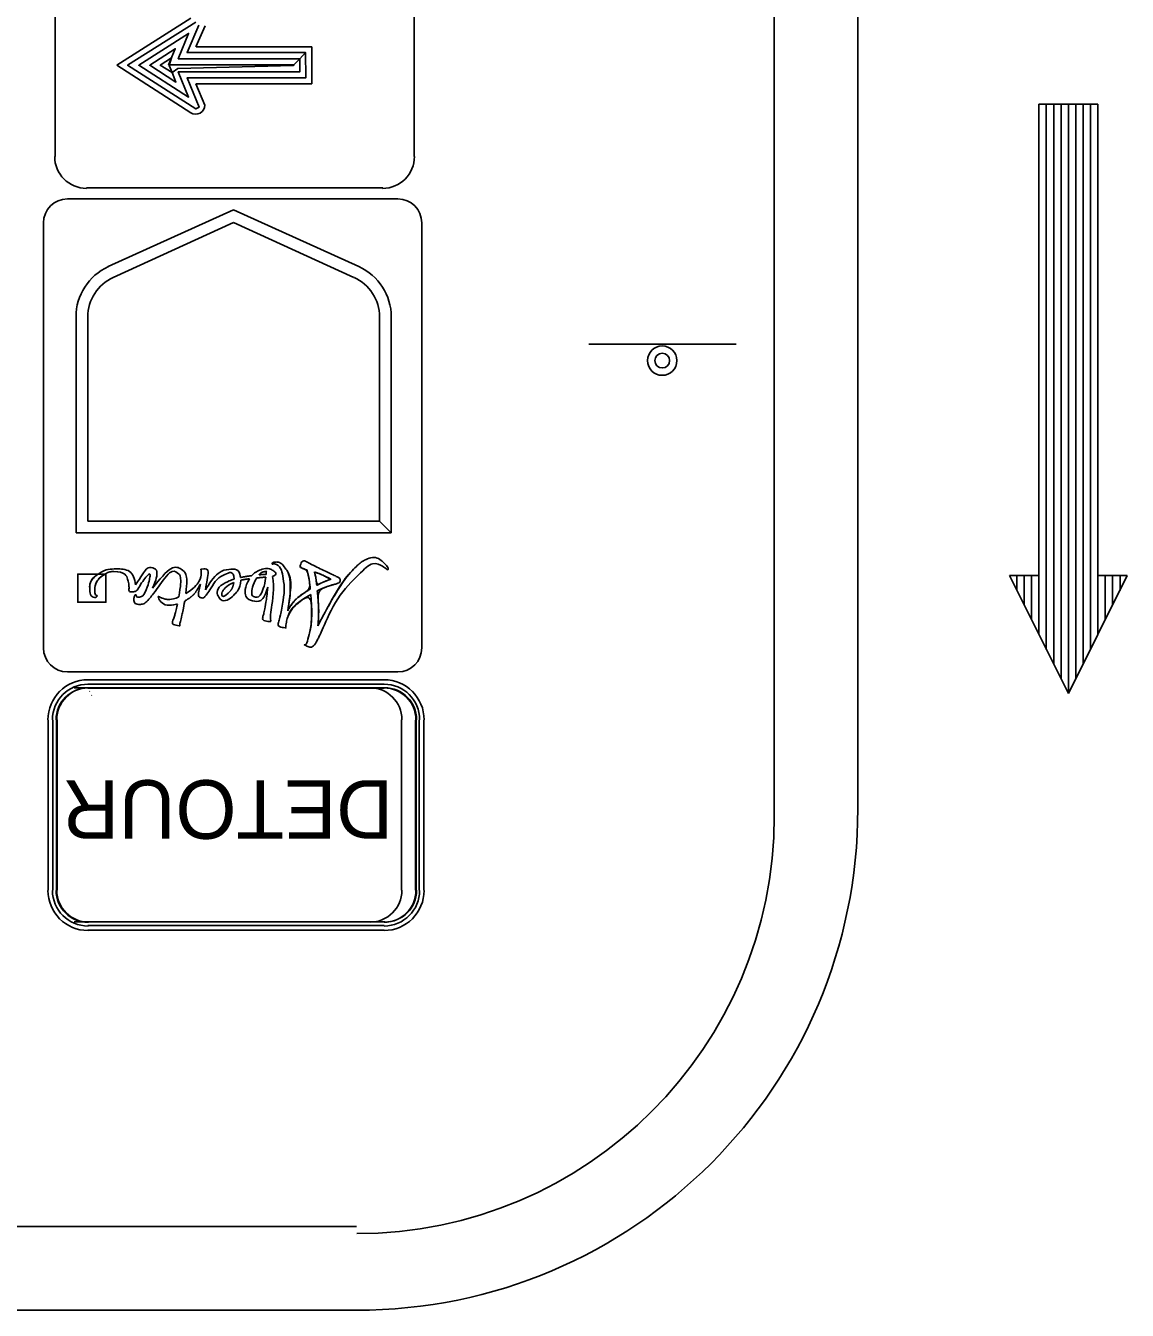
# Model space of a CAD drawing. Extents: x 1806 to 2022, y 110 to 389.
# Drawn here: x 1952.54 to 1968.49, y 225.81 to 244.41 of the extents above; entities that cross this region are included whole.
import ezdxf

# ---------------------------------------------------------------- set-up
doc = ezdxf.new("R2010")
doc.units = 0
for name, color, linetype in [('Level 10', 7, 'Continuous'), ('Level 2', 7, 'Continuous'), ('Level 44', 7, 'Continuous'), ('Level 50', 7, 'Continuous'), ('Level 53', 7, 'Continuous')]:
    doc.layers.add(name, color=color, linetype=linetype)

msp = doc.modelspace()

# ---------------------------------------------------------------- linework, layer by layer
at = {"layer": 'Level 10'}
for p, q in [((1963.38, 232.973), (1963.38, 272.1)), ((1964.59, 233.074), (1964.59, 272.1)), ((1957.331, 227.026), (1895.86, 227.026)), ((1957.331, 225.815), (1895.86, 225.815))]:
    msp.add_line(p, q, dxfattribs=at)
for centre, radius in [((1957.332, 233.074), 7.258), ((1957.332, 232.973), 6.048)]:
    msp.add_arc(centre, radius, 270, 360, dxfattribs=at)
at = {"layer": 'Level 2'}
for p, q in [((1957.928, 241.904), (1953.143, 241.904)), ((1953.735, 240.923), (1955.55, 241.748)), ((1955.55, 241.748), (1957.364, 240.923)), ((1952.796, 235.403), (1952.796, 241.557)), ((1955.55, 241.56), (1953.806, 240.767)), ((1957.293, 240.767), (1955.55, 241.56)), ((1958.275, 235.403), (1958.275, 241.557)), ((1953.267, 237.068), (1953.267, 240.196)), ((1953.438, 240.196), (1953.438, 237.24)), ((1957.661, 237.24), (1957.661, 240.196)), ((1957.833, 240.196), (1957.833, 237.068)), ((1953.438, 237.24), (1957.661, 237.24)), ((1957.833, 237.068), (1957.661, 237.24)), ((1957.661, 237.24), (1957.833, 237.068)), ((1957.833, 237.068), (1953.267, 237.068)), ((1957.928, 235.056), (1953.143, 235.056)), ((1957.928, 235.056), (1953.143, 235.056))]:
    msp.add_line(p, q, dxfattribs=at)
for centre, radius, start, end in [((1953.143, 241.557), 0.347, 90, 180), ((1957.928, 241.557), 0.347, 360, 90), ((1954.066, 240.196), 0.799, 114.4568, 180), ((1957.034, 240.196), 0.799, 360, 65.5432), ((1954.066, 240.196), 0.628, 114.4568, 180), ((1957.034, 240.196), 0.628, 360, 65.5432), ((1953.143, 235.403), 0.347, 180, 270), ((1957.928, 235.403), 0.347, 270, 360)]:
    msp.add_arc(centre, radius, start, end, dxfattribs=at)
at = {"layer": 'Level 44'}
for p, q in [((1952.964, 244.984), (1952.964, 242.519)), ((1958.163, 242.519), (1958.163, 244.984)), ((1954.931, 244.522), (1953.856, 243.839)), ((1955.004, 244.103), (1955.136, 244.411)), ((1956.681, 244.103), (1955.008, 244.103)), ((1956.681, 243.57), (1956.681, 244.103)), ((1953.856, 243.839), (1954.931, 243.152)), ((1955.132, 243.263), (1955.004, 243.57)), ((1955.004, 243.57), (1956.681, 243.57)), ((1953.42, 242.062), (1957.711, 242.062)), ((1962.828, 239.802), (1960.695, 239.802)), ((1953.437, 234.942), (1957.728, 234.942)), ((1953.437, 234.877), (1957.728, 234.877)), ((1957.529, 234.825), (1953.238, 234.825)), ((1953.441, 234.825), (1953.437, 234.823)), ((1953.437, 234.823), (1957.728, 234.823)), ((1953.437, 234.823), (1957.728, 234.823)), ((1953.447, 234.825), (1957.738, 234.825)), ((1953.465, 234.777), (1953.461, 234.775)), ((1953.494, 234.719), (1953.49, 234.717)), ((1955.362, 234.829), (1955.362, 234.829)), ((1955.362, 234.829), (1955.362, 234.829)), ((1955.372, 234.831), (1955.372, 234.831)), ((1955.604, 234.831), (1955.604, 234.831)), ((1952.866, 231.895), (1952.866, 234.36)), ((1952.931, 231.895), (1952.931, 234.36)), ((1952.985, 231.895), (1952.985, 234.36)), ((1952.985, 231.895), (1952.985, 234.36)), ((1952.995, 231.897), (1952.995, 234.362)), ((1957.981, 231.897), (1957.981, 234.362)), ((1958.184, 234.36), (1958.184, 231.895)), ((1958.184, 234.36), (1958.184, 231.895)), ((1958.194, 234.362), (1958.194, 231.897)), ((1958.238, 234.36), (1958.238, 231.895)), ((1958.303, 234.36), (1958.303, 231.895)), ((1953.238, 231.441), (1957.529, 231.441)), ((1957.728, 231.439), (1953.437, 231.439)), ((1957.728, 231.439), (1953.437, 231.439)), ((1957.728, 231.385), (1953.437, 231.385)), ((1957.738, 231.441), (1953.447, 231.441)), ((1957.728, 231.32), (1953.437, 231.32))]:
    msp.add_line(p, q, dxfattribs=at)
for points in [[(1955, 244.462), (1954.014, 243.839), (1955.004, 243.207), (1955.051, 243.233), (1954.876, 243.655), (1956.595, 243.655), (1956.591, 244.022), (1956.51, 243.933), (1954.748, 243.933), (1954.897, 244.3), (1954.176, 243.839), (1954.897, 243.378), (1954.748, 243.745), (1956.51, 243.745), (1956.51, 243.933), (1956.42, 243.847), (1954.607, 243.847), (1954.705, 244.078), (1954.334, 243.839), (1954.714, 243.596), (1954.658, 243.732), (1954.488, 243.839), (1954.65, 243.946), (1954.616, 243.835), (1954.658, 243.732), (1954.744, 243.792), (1956.416, 243.835), (1956.42, 243.847)], [(1956.591, 244.022), (1954.876, 244.022), (1955.046, 244.419)], [(1956.591, 244.022), (1954.876, 244.022)]]:
    msp.add_lwpolyline(points, dxfattribs=at)
for radius in [0.213, 0.107]:
    msp.add_circle((1961.757, 239.563), radius, dxfattribs=at)
for centre, radius, start, end in [((1955, 243.263), 0.132, 237.5014, 359.8949), ((1953.42, 242.518), 0.462, 180, 270), ((1957.707, 242.518), 0.462, 270, 0), ((1953.441, 234.363), 0.581, 90, 180), ((1953.441, 234.363), 0.516, 90, 180), ((1957.728, 234.363), 0.581, 0, 90), ((1957.728, 234.363), 0.516, 0, 90), ((1953.441, 234.363), 0.462, 90, 180), ((1953.441, 234.363), 0.462, 90, 180), ((1953.451, 234.365), 0.462, 90, 180), ((1957.525, 234.365), 0.462, 0, 90), ((1957.728, 234.363), 0.462, 0, 90), ((1957.728, 234.363), 0.462, 0, 90), ((1957.738, 234.365), 0.462, 0, 90), ((1953.451, 231.896), 0.462, 180, 270), ((1957.525, 231.896), 0.462, 270, 0), ((1957.738, 231.896), 0.462, 270, 360), ((1953.441, 231.894), 0.581, 180, 270), ((1953.441, 231.894), 0.516, 180, 270), ((1953.441, 231.894), 0.462, 180, 270), ((1953.441, 231.894), 0.462, 180, 270), ((1957.728, 231.894), 0.462, 270, 360), ((1957.728, 231.894), 0.581, 270, 360), ((1957.728, 231.894), 0.516, 270, 360), ((1957.728, 231.894), 0.462, 270, 360)]:
    msp.add_arc(centre, radius, start, end, dxfattribs=at)
at = {"layer": 'Level 50'}
for p, q in [((1967.213, 236.45), (1967.213, 243.276)), ((1968.067, 243.276), (1967.213, 243.276)), ((1967.213, 235.596), (1967.213, 243.276)), ((1967.32, 235.383), (1967.32, 243.276)), ((1967.427, 235.17), (1967.427, 243.276)), ((1967.533, 234.956), (1967.533, 243.276)), ((1967.64, 234.743), (1967.64, 243.276)), ((1967.747, 234.956), (1967.747, 243.276)), ((1967.853, 235.17), (1967.853, 243.276)), ((1967.96, 235.383), (1967.96, 243.276)), ((1968.067, 236.45), (1968.067, 243.276)), ((1968.067, 235.596), (1968.067, 243.276)), ((1967.64, 234.743), (1966.787, 236.45)), ((1967.213, 236.45), (1966.787, 236.45)), ((1966.893, 236.236), (1966.893, 236.45)), ((1967, 236.023), (1967, 236.45)), ((1967.107, 235.81), (1967.107, 236.45)), ((1967.64, 234.743), (1968.493, 236.45)), ((1968.493, 236.45), (1968.067, 236.45)), ((1968.173, 235.81), (1968.173, 236.45)), ((1968.28, 236.023), (1968.28, 236.45)), ((1968.387, 236.236), (1968.387, 236.45))]:
    msp.add_line(p, q, dxfattribs=at)
at = {"layer": 'Level 53'}
msp.add_line((1953.587, 236.473), (1953.687, 236.473), dxfattribs=at)
msp.add_lwpolyline([(1953.587, 236.473), (1953.292, 236.473), (1953.292, 236.066), (1953.699, 236.066), (1953.699, 236.473), (1953.687, 236.473)], dxfattribs=at)
for points, degree in [([(1954.13, 236.318), (1954.12, 236.402), (1954.064, 236.547), (1953.838, 236.547), (1953.737, 236.547), (1953.651, 236.518), (1953.587, 236.473)], 3), ([(1954.377, 236.269), (1954.429, 236.387), (1954.459, 236.538), (1954.38, 236.561), (1954.288, 236.588), (1954.215, 236.435), (1954.13, 236.318)], 3), ([(1954.858, 236.193), (1954.876, 236.351), (1954.87, 236.492), (1954.798, 236.537), (1954.666, 236.619), (1954.48, 236.402), (1954.377, 236.269)], 3), ([(1955.143, 236.245), (1955.153, 236.343), (1955.216, 236.557), (1955.108, 236.546), (1955.065, 236.542), (1955.084, 236.535), (1955.081, 236.498), (1955.072, 236.369), (1954.964, 236.26), (1954.858, 236.193)], 3), ([(1955.651, 236.424), (1955.642, 236.496), (1955.596, 236.551), (1955.487, 236.54), (1955.332, 236.526), (1955.195, 236.336), (1955.143, 236.245)], 3), ([(1956.112, 236.44), (1956.158, 236.455), (1956.177, 236.489), (1956.118, 236.526), (1956.077, 236.551), (1955.988, 236.559), (1955.897, 236.515), (1955.865, 236.499), (1955.837, 236.476), (1955.813, 236.45)], 3), ([(1956.141, 236.621), (1956.185, 236.614), (1956.242, 236.555), (1956.259, 236.457), (1956.291, 236.28), (1956.272, 236.106), (1956.22, 235.846), (1956.211, 235.797), (1956.177, 235.712), (1956.284, 235.696), (1956.317, 235.691), (1956.3, 235.707), (1956.309, 235.752), (1956.35, 235.945), (1956.508, 236.085), (1956.667, 236.178), (1956.684, 235.957), (1956.677, 235.711), (1956.635, 235.56), (1956.6, 235.433), (1956.558, 235.457), (1956.61, 235.43), (1956.665, 235.402), (1956.723, 235.439), (1956.771, 235.534), (1956.818, 235.628), (1957.037, 236.143), (1957.386, 236.49), (1957.565, 236.667), (1957.726, 236.576), (1957.759, 236.549), (1957.785, 236.526), (1957.795, 236.561), (1957.762, 236.596), (1957.617, 236.752), (1957.406, 236.662), (1957.33, 236.585), (1957.117, 236.373), (1956.87, 235.916), (1956.77, 235.722), (1956.78, 235.831), (1956.783, 236.014), (1956.762, 236.229), (1956.87, 236.282), (1956.967, 236.313), (1957.013, 236.325), (1957.063, 236.338), (1957.093, 236.358), (1957.094, 236.381), (1957.095, 236.406), (1957.062, 236.427), (1957.014, 236.45), (1956.928, 236.49), (1956.678, 236.609), (1956.616, 236.645), (1956.563, 236.675), (1956.537, 236.651), (1956.522, 236.618), (1956.501, 236.575), (1956.557, 236.55), (1956.612, 236.534), (1956.632, 236.461), (1956.649, 236.364), (1956.66, 236.256), (1956.533, 236.177), (1956.408, 236.073), (1956.335, 235.943), (1956.353, 236.052), (1956.4, 236.422), (1956.283, 236.579), (1956.257, 236.614), (1956.2, 236.652), (1956.145, 236.646), (1956.119, 236.643), (1956.105, 236.626), (1956.108, 236.621), (1956.111, 236.615), (1956.126, 236.623), (1956.141, 236.621)], 3), ([(1956.335, 235.943), (1956.353, 236.052), (1956.4, 236.422), (1956.283, 236.579), (1956.257, 236.614), (1956.2, 236.652), (1956.145, 236.646), (1956.119, 236.643), (1956.105, 236.626), (1956.108, 236.621), (1956.111, 236.615), (1956.126, 236.623), (1956.141, 236.621)], 3), ([(1956.141, 236.621), (1956.185, 236.614), (1956.242, 236.555), (1956.259, 236.457), (1956.291, 236.28), (1956.272, 236.106), (1956.22, 235.846), (1956.211, 235.797), (1956.177, 235.712), (1956.284, 235.696), (1956.317, 235.691), (1956.3, 235.707), (1956.309, 235.752), (1956.35, 235.945), (1956.508, 236.085), (1956.667, 236.178)], 3), ([(1956.762, 236.229), (1956.87, 236.282), (1956.967, 236.313), (1957.013, 236.325), (1957.063, 236.338), (1957.093, 236.358), (1957.094, 236.381), (1957.095, 236.406), (1957.062, 236.427), (1957.014, 236.45), (1956.928, 236.49), (1956.678, 236.609), (1956.616, 236.645), (1956.563, 236.675), (1956.537, 236.651), (1956.522, 236.618), (1956.501, 236.575), (1956.557, 236.55), (1956.612, 236.534)], 3), ([(1956.667, 236.178), (1956.684, 235.957), (1956.677, 235.711), (1956.635, 235.56), (1956.6, 235.433), (1956.558, 235.457), (1956.61, 235.43), (1956.665, 235.402), (1956.723, 235.439), (1956.771, 235.534), (1956.818, 235.628), (1957.037, 236.143), (1957.386, 236.49), (1957.565, 236.667), (1957.726, 236.576), (1957.759, 236.549), (1957.785, 236.526), (1957.795, 236.561), (1957.762, 236.596), (1957.617, 236.752), (1957.406, 236.662), (1957.33, 236.585), (1957.117, 236.373), (1956.87, 235.916), (1956.77, 235.722)], 3), ([(1953.699, 236.066), (1953.699, 236.066), (1953.699, 236.473), (1953.699, 236.473), (1953.699, 236.473), (1953.687, 236.473), (1953.687, 236.473), (1953.599, 236.42), (1953.539, 236.319), (1953.54, 236.235), (1953.54, 236.164), (1953.578, 236.167), (1953.573, 236.157), (1953.561, 236.128), (1953.471, 236.145), (1953.466, 236.246), (1953.461, 236.332), (1953.506, 236.416), (1953.587, 236.473), (1953.587, 236.473), (1953.292, 236.473), (1953.292, 236.473), (1953.292, 236.473), (1953.292, 236.066), (1953.292, 236.066), (1953.292, 236.066), (1953.699, 236.066), (1953.699, 236.066)], 3), ([(1953.687, 236.473), (1953.599, 236.42), (1953.539, 236.319), (1953.54, 236.235), (1953.54, 236.164), (1953.578, 236.167), (1953.573, 236.157), (1953.561, 236.128), (1953.471, 236.145), (1953.466, 236.246), (1953.461, 236.332), (1953.506, 236.416), (1953.587, 236.473)], 3), ([(1953.687, 236.473), (1953.725, 236.495), (1953.768, 236.509), (1953.813, 236.509)], 2), ([(1953.813, 236.509), (1953.98, 236.509), (1954.024, 236.379), (1954.032, 236.315), (1954.037, 236.272), (1954.028, 236.21), (1954.102, 236.218), (1954.153, 236.224), (1954.2, 236.325), (1954.266, 236.41), (1954.322, 236.482), (1954.347, 236.475), (1954.334, 236.413), (1954.318, 236.335), (1954.252, 236.151), (1954.178, 236.138), (1954.143, 236.132), (1954.131, 236.192), (1954.115, 236.154), (1954.099, 236.116), (1954.114, 236.034), (1954.191, 236.034), (1954.245, 236.034), (1954.31, 236.091), (1954.363, 236.157), (1954.41, 236.214), (1954.644, 236.559), (1954.743, 236.485), (1954.789, 236.45), (1954.785, 236.308), (1954.756, 236.141)], 3), ([(1955.068, 236.325), (1955.058, 236.275), (1955.042, 236.219), (1955.041, 236.181), (1955.04, 236.142), (1955.067, 236.133), (1955.077, 236.13), (1955.1, 236.123), (1955.128, 236.135), (1955.156, 236.173), (1955.22, 236.264), (1955.302, 236.408), (1955.426, 236.468), (1955.515, 236.512), (1955.554, 236.468), (1955.556, 236.401)], 3), ([(1955.556, 236.401), (1955.539, 236.396), (1955.523, 236.39), (1955.51, 236.384), (1955.349, 236.313), (1955.293, 236.205), (1955.334, 236.139), (1955.373, 236.077), (1955.484, 236.096), (1955.572, 236.188), (1955.615, 236.234), (1955.649, 236.312), (1955.653, 236.384)], 3), ([(1955.813, 236.45), (1955.76, 236.443), (1955.703, 236.434), (1955.651, 236.424)], 2), ([(1955.653, 236.384), (1955.69, 236.392), (1955.733, 236.399), (1955.78, 236.405)], 2), ([(1955.78, 236.405), (1955.705, 236.282), (1955.711, 236.116), (1955.822, 236.088), (1955.95, 236.056), (1956.015, 236.18), (1956.043, 236.284)], 3), ([(1956.015, 236.429), (1955.998, 236.298), (1955.93, 236.116), (1955.845, 236.146), (1955.797, 236.162), (1955.822, 236.315), (1955.885, 236.417)], 3), ([(1955.885, 236.417), (1955.926, 236.421), (1955.97, 236.425), (1956.015, 236.429)], 2), ([(1955.918, 236.461), (1955.94, 236.486), (1955.965, 236.503), (1955.992, 236.507)], 2), ([(1956.019, 236.469), (1955.996, 236.468), (1955.96, 236.466), (1955.918, 236.461)], 2), ([(1956.043, 236.284), (1956.035, 236.18), (1956.018, 236.054), (1955.994, 235.937), (1955.985, 235.888), (1955.951, 235.802), (1956.058, 235.786), (1956.092, 235.781), (1956.086, 235.797), (1956.083, 235.842), (1956.08, 235.904), (1956.148, 236.276), (1956.112, 236.44)], 3), ([(1955.992, 236.507), (1956.007, 236.51), (1956.02, 236.509), (1956.029, 236.508)], 2), ([(1956.029, 236.508), (1956.023, 236.503), (1956.02, 236.495), (1956.02, 236.487), (1956.02, 236.481), (1956.02, 236.475), (1956.019, 236.469)], 3), ([(1956.612, 236.534), (1956.632, 236.461), (1956.649, 236.364), (1956.66, 236.256)], 2), ([(1956.754, 236.309), (1956.744, 236.395), (1956.733, 236.458), (1956.72, 236.504)], 2), ([(1956.72, 236.504), (1956.776, 236.484), (1956.855, 236.452), (1956.958, 236.399)], 2), ([(1956.958, 236.399), (1956.901, 236.379), (1956.829, 236.349), (1956.754, 236.309), (1956.744, 236.395), (1956.733, 236.458), (1956.72, 236.504), (1956.776, 236.484), (1956.855, 236.452), (1956.958, 236.399)], 3), ([(1956.958, 236.399), (1956.901, 236.379), (1956.829, 236.349), (1956.754, 236.309)], 2), ([(1954.842, 236.083), (1954.928, 236.132), (1955.009, 236.216), (1955.068, 236.325)], 2), ([(1955.47, 236.197), (1955.416, 236.146), (1955.389, 236.15), (1955.382, 236.163), (1955.367, 236.193), (1955.431, 236.295), (1955.552, 236.352)], 3), ([(1955.552, 236.352), (1955.542, 236.296), (1955.513, 236.236), (1955.47, 236.197)], 2), ([(1956.66, 236.256), (1956.533, 236.177), (1956.408, 236.073), (1956.335, 235.943)], 2), ([(1956.77, 235.722), (1956.78, 235.831), (1956.783, 236.014), (1956.762, 236.229)], 2), ([(1954.756, 236.141), (1954.639, 236.096), (1954.542, 236.11), (1954.487, 236.137), (1954.46, 236.15), (1954.456, 236.148), (1954.468, 236.118), (1954.485, 236.074), (1954.579, 236.006), (1954.726, 236.037), (1954.729, 236.038), (1954.733, 236.039), (1954.736, 236.039)], 3), ([(1954.736, 236.039), (1954.725, 235.985), (1954.711, 235.93), (1954.696, 235.876), (1954.682, 235.827), (1954.642, 235.742), (1954.747, 235.726), (1954.78, 235.721), (1954.766, 235.737), (1954.777, 235.782), (1954.798, 235.866), (1954.823, 235.974), (1954.842, 236.083)], 3)]:
    msp.add_open_spline(points, degree=degree, dxfattribs=at)

# ---------------------------------------------------------------- texts
at = {"layer": 'Level 44'}
msp.add_text('DETOUR', height=0.8479, rotation=180, dxfattribs=at).set_placement((1957.857, 233.489))

doc.saveas('drawing.dxf')
